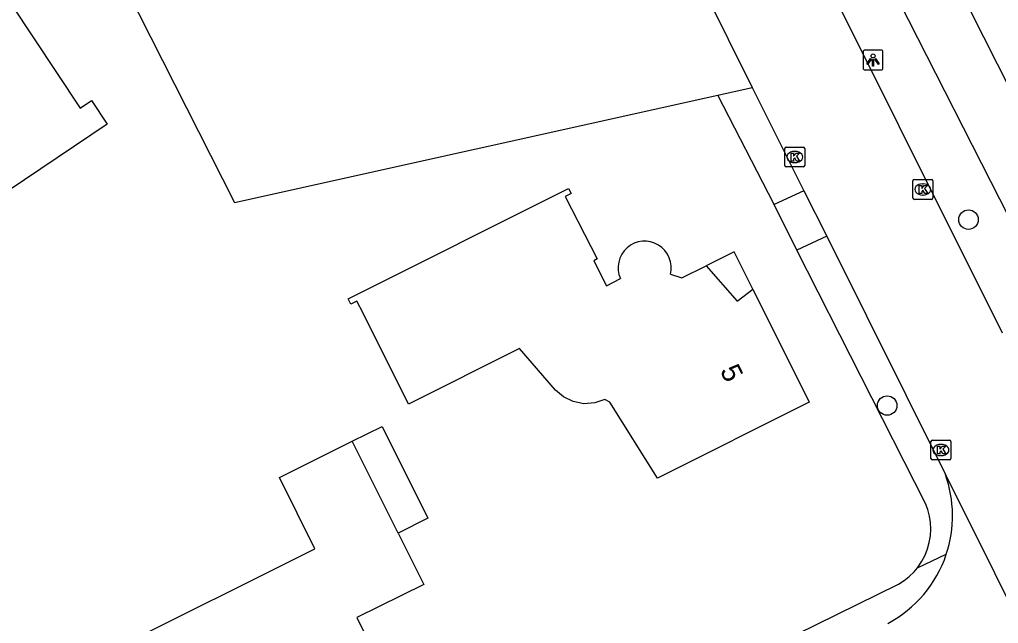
# Model space of a CAD drawing. Extents: x 157321 to 158827, y 386650 to 388532.
# Drawn here: x 158190.6 to 158239.72, y 387151.98 to 387182.26 of the extents above; entities that cross this region are included whole.
import ezdxf

# ---------------------------------------------------------------- set-up
doc = ezdxf.new("R2010")
doc.units = 0
for name, color, linetype in [('IMGEO_Berm_groen', 7, 'Continuous'), ('IMGEO_Boom', 7, 'Continuous'), ('IMGEO_Groenvoorziening', 7, 'Continuous'), ('IMGEO_Kolk', 7, 'Continuous'), ('IMGEO_Lichtpunt', 7, 'Continuous'), ('IMGEO_Pand', 7, 'Continuous'), ('IMGEO_Pand_nummerreeks', 7, 'Continuous'), ('IMGEO_Pand_overbouw', 7, 'Continuous'), ('IMGEO_Parkeervlak_open', 7, 'Continuous'), ('IMGEO_Rijbaan_lokaal_gesloten', 7, 'Continuous'), ('IMGEO_Voetpad_open', 7, 'Continuous')]:
    doc.layers.add(name, color=color, linetype=linetype)

msp = doc.modelspace()

# ---------------------------------------------------------------- linework, layer by layer
at = {"layer": 'IMGEO_Berm_groen'}
msp.add_lwpolyline([(158232.002, 387188.552), (158242.522, 387167.891)], dxfattribs=at)
at = {"layer": 'IMGEO_Boom'}
for centre in [(158238.22, 387172.232), (158234.139, 387162.905)]:
    msp.add_circle(centre, 0.489, dxfattribs=at)
at = {"layer": 'IMGEO_Groenvoorziening'}
for points in [[(158228.461, 387172.993), (158225.64, 387178.479)], [(158235.655, 387154.773), (158235.883, 387155.106), (158236.038, 387155.403), (158236.16, 387155.714), (158236.249, 387156.036), (158236.304, 387156.365), (158236.324, 387156.699), (158236.31, 387157.033), (158236.26, 387157.364), (158236.176, 387157.687), (158236.059, 387158), (158229.598, 387170.706)], [(158235.655, 387154.773), (158237.106, 387155.45)], [(158215.288, 387144.405), (158234.705, 387153.947), (158234.987, 387154.127), (158235.248, 387154.335), (158235.487, 387154.569), (158235.655, 387154.773)]]:
    msp.add_lwpolyline(points, dxfattribs=at)
at = {"layer": 'IMGEO_Kolk'}
for p, q in [((158228.998, 387174.945), (158228.998, 387175.797)), ((158229.073, 387175.871), (158229.925, 387175.871)), ((158229.486, 387175.651), (158229.511, 387175.651)), ((158229.999, 387175.797), (158229.999, 387174.945)), ((158229.925, 387174.871), (158229.073, 387174.871)), ((158229.509, 387175.091), (158229.484, 387175.091)), ((158235.427, 387173.318), (158235.427, 387174.17)), ((158235.502, 387174.244), (158236.354, 387174.244)), ((158236.428, 387174.17), (158236.428, 387173.318)), ((158235.915, 387174.024), (158235.94, 387174.024)), ((158236.354, 387173.244), (158235.502, 387173.244)), ((158235.938, 387173.464), (158235.913, 387173.464)), ((158236.335, 387160.25), (158236.335, 387161.102)), ((158236.41, 387161.176), (158237.262, 387161.176)), ((158236.823, 387160.956), (158236.848, 387160.956)), ((158237.336, 387161.102), (158237.336, 387160.25)), ((158237.262, 387160.176), (158236.41, 387160.176)), ((158236.846, 387160.396), (158236.821, 387160.396))]:
    msp.add_line(p, q, dxfattribs=at)
for points in [[(158228.998, 387174.945), (158228.998, 387175.797)], [(158229.073, 387175.871), (158229.925, 387175.871)], [(158229.999, 387175.797), (158229.999, 387174.945)], [(158229.319, 387175.571), (158229.442, 387175.571), (158229.442, 387175.42), (158229.572, 387175.571), (158229.736, 387175.571), (158229.59, 387175.42), (158229.743, 387175.171), (158229.591, 387175.171), (158229.506, 387175.335), (158229.442, 387175.268), (158229.442, 387175.171), (158229.319, 387175.171), (158229.319, 387175.571)], [(158229.925, 387174.871), (158229.073, 387174.871)], [(158235.427, 387173.318), (158235.427, 387174.17)], [(158235.502, 387174.244), (158236.354, 387174.244)], [(158236.428, 387174.17), (158236.428, 387173.318)], [(158235.748, 387173.944), (158235.871, 387173.944), (158235.871, 387173.793), (158236.001, 387173.944), (158236.165, 387173.944), (158236.019, 387173.793), (158236.172, 387173.544), (158236.02, 387173.544), (158235.935, 387173.708), (158235.871, 387173.641), (158235.871, 387173.544), (158235.748, 387173.544), (158235.748, 387173.944)], [(158236.354, 387173.244), (158235.502, 387173.244)], [(158236.335, 387160.25), (158236.335, 387161.102)], [(158236.41, 387161.176), (158237.262, 387161.176)], [(158237.336, 387161.102), (158237.336, 387160.25)], [(158236.656, 387160.876), (158236.779, 387160.876), (158236.779, 387160.725), (158236.909, 387160.876), (158237.073, 387160.876), (158236.927, 387160.725), (158237.08, 387160.476), (158236.928, 387160.476), (158236.843, 387160.64), (158236.779, 387160.573), (158236.779, 387160.476), (158236.656, 387160.476), (158236.656, 387160.876)], [(158237.262, 387160.176), (158236.41, 387160.176)]]:
    msp.add_lwpolyline(points, dxfattribs=at)
for centre, start, end in [((158229.075, 387175.795), 91.552, 178.448), ((158229.075, 387175.795), 91.552, 178.448), ((158229.923, 387175.795), 1.552, 88.448), ((158229.923, 387175.795), 1.552, 88.448), ((158229.075, 387174.947), 181.552, 268.448), ((158229.075, 387174.947), 181.552, 268.448), ((158229.923, 387174.947), 271.552, 358.448), ((158229.923, 387174.947), 271.552, 358.448), ((158235.504, 387174.168), 91.552, 178.448), ((158235.504, 387174.168), 91.552, 178.448), ((158236.352, 387174.168), 1.552, 88.448), ((158236.352, 387174.168), 1.552, 88.448), ((158235.504, 387173.32), 181.552, 268.448), ((158235.504, 387173.32), 181.552, 268.448), ((158236.352, 387173.32), 271.552, 358.448), ((158236.352, 387173.32), 271.552, 358.448), ((158236.412, 387161.1), 91.552, 178.448), ((158236.412, 387161.1), 91.552, 178.448), ((158237.26, 387161.1), 1.552, 88.448), ((158237.26, 387161.1), 1.552, 88.448), ((158236.412, 387160.252), 181.552, 268.448), ((158236.412, 387160.252), 181.552, 268.448), ((158237.26, 387160.252), 271.552, 358.448), ((158237.26, 387160.252), 271.552, 358.448)]:
    msp.add_arc(centre, 0.0765, start, end, dxfattribs=at)
for centre, major_axis, ratio, start_param, end_param in [((158229.485, 387175.371), (-0.387, 0.002), 0.722429, 4.712389, 7.853982), ((158229.51, 387175.371), (-0.39, 0.002), 0.717154, 1.570796, 4.712389), ((158235.914, 387173.744), (-0.387, 0.002), 0.722429, 4.712389, 7.853982), ((158235.939, 387173.744), (-0.39, 0.002), 0.717154, 1.570796, 4.712389), ((158236.822, 387160.676), (-0.387, 0.002), 0.722429, 4.712389, 7.853982), ((158236.847, 387160.676), (-0.39, 0.002), 0.717154, 1.570796, 4.712389)]:
    msp.add_ellipse(centre, major_axis=major_axis, ratio=ratio, start_param=start_param, end_param=end_param, dxfattribs=at)
at = {"layer": 'IMGEO_Lichtpunt'}
for p, q in [((158232.931, 387180.641), (158232.931, 387179.834)), ((158232.931, 387180.641), (158232.931, 387179.834)), ((158233.833, 387180.736), (158233.025, 387180.736)), ((158233.833, 387180.736), (158233.025, 387180.736)), ((158233.927, 387179.834), (158233.927, 387180.641)), ((158233.927, 387179.834), (158233.927, 387180.641)), ((158233.025, 387179.74), (158233.833, 387179.74)), ((158233.025, 387179.74), (158233.833, 387179.74))]:
    msp.add_line(p, q, dxfattribs=at)
for points in [[(158233.305, 387180.305), (158233.344, 387180.277), (158233.156, 387180.015), (158233.118, 387180.042), (158233.305, 387180.305)], [(158233.407, 387180.257), (158233.454, 387180.257), (158233.454, 387179.935), (158233.407, 387179.935), (158233.407, 387180.257)], [(158233.517, 387180.277), (158233.555, 387180.304), (158233.742, 387180.042), (158233.703, 387180.014), (158233.517, 387180.277)]]:
    msp.add_lwpolyline(points, dxfattribs=at)
msp.add_circle((158233.43, 387180.439), 0.0994, dxfattribs=at)
for centre, start, end in [((158233.025, 387180.641), 90, 180), ((158233.025, 387180.641), 90, 180), ((158233.833, 387180.641), 0, 90), ((158233.833, 387180.641), 0, 90), ((158233.025, 387179.834), 180, 270), ((158233.025, 387179.834), 180, 270), ((158233.833, 387179.834), 270, 0), ((158233.833, 387179.834), 270, 360)]:
    msp.add_arc(centre, 0.0946, start, end, dxfattribs=at)
at = {"layer": 'IMGEO_Pand'}
for points in [[(158251.152, 387195.446), (158248.734, 387194.228), (158243.529, 387191.607), (158247.974, 387182.784), (158253.142, 387185.384), (158255.644, 387180.411), (158248.283, 387176.708), (158243.816, 387174.461), (158241.391, 387179.203), (158240.357, 387178.677), (158236.258, 387186.782), (158237.319, 387187.324), (158238.237, 387187.793), (158237.424, 387189.402), (158236.508, 387188.936), (158235.792, 387190.374), (158237.759, 387191.367), (158235.863, 387195.124), (158245.553, 387200.004), (158245.769, 387200.113), (158248.099, 387201.286), (158249.098, 387199.374)], [(158178.524, 387186.149), (158176.322, 387190.638), (158179.847, 387192.398), (158179.547, 387192.866), (158183.49, 387195.479), (158184.978, 387193.274), (158187.23, 387194.407), (158191.447, 387186.111), (158189.583, 387185.163), (158188.965, 387184.849), (158193.64, 387177.822), (158194.214, 387178.203), (158195, 387177.021), (158190.851, 387174.232), (158188.72, 387172.8), (158181.916, 387182.662), (158180.559, 387181.999), (158178.524, 387186.149)], [(158223.256, 387169.49), (158223.831, 387169.306), (158225.06, 387169.919), (158226.609, 387168.146), (158227.398, 387168.743), (158230.223, 387163.077), (158222.613, 387159.264), (158220.226, 387163.082), (158219.975, 387163.212), (158219.463, 387163.037), (158218.911, 387162.987), (158218.376, 387163.107), (158217.894, 387163.345), (158217.497, 387163.682), (158215.687, 387165.76), (158210.123, 387162.978), (158207.833, 387167.531), (158207.523, 387168.147), (158207.22, 387167.996), (158207.086, 387168.264), (158218.142, 387173.797)], [(158218.142, 387173.797), (158218.272, 387173.54), (158217.983, 387173.394), (158219.58, 387170.262), (158219.41, 387170.158), (158220.045, 387168.915), (158220.748, 387169.275)], [(158207.296, 387161.111), (158208.786, 387161.852), (158211.081, 387157.26), (158209.598, 387156.506)], [(158209.598, 387156.506), (158210.886, 387153.93), (158207.518, 387152.267), (158208.863, 387149.543), (158209.551, 387148.149), (158199.073, 387142.942), (158196.835, 387147.413), (158195.221, 387150.638), (158205.418, 387155.712), (158203.638, 387159.29), (158207.296, 387161.111)], [(158209.598, 387156.506), (158207.296, 387161.111)]]:
    msp.add_lwpolyline(points, dxfattribs=at)
msp.add_arc((158221.965, 387169.818), 1.332, 345.7324, 204.0671, dxfattribs=at)
at = {"layer": 'IMGEO_Pand_overbouw'}
msp.add_lwpolyline([(158226.463, 387170.619), (158225.06, 387169.919), (158226.609, 387168.146), (158227.398, 387168.743)], close=True, dxfattribs=at)
at = {"layer": 'IMGEO_Parkeervlak_open'}
for points in [[(158180.674, 387214.601), (158180.644, 387214.276), (158193.399, 387188.847), (158194.761, 387186.161), (158201.391, 387173.082), (158225.64, 387178.479)], [(158225.64, 387178.479), (158227.354, 387178.86)]]:
    msp.add_lwpolyline(points, dxfattribs=at)
at = {"layer": 'IMGEO_Rijbaan_lokaal_gesloten'}
for points in [[(158222.532, 387188.602), (158227.354, 387178.86)], [(158239.92, 387166.54), (158229.541, 387187.344)], [(158227.354, 387178.86), (158229.963, 387173.679)], [(158229.963, 387173.679), (158231.104, 387171.408)], [(158231.104, 387171.408), (158237.057, 387159.45)], [(158237.057, 387159.45), (158244.461, 387144.615)]]:
    msp.add_lwpolyline(points, dxfattribs=at)
for centre, radius, start, end in [((158231.306, 387157.379), 6.112, 341.6008, 19.8029), ((158231.303, 387157.381), 6.116, 297.9326, 341.5917)]:
    msp.add_arc(centre, radius, start, end, dxfattribs=at)
at = {"layer": 'IMGEO_Voetpad_open'}
for points in [[(158229.963, 387173.679), (158228.461, 387172.993)], [(158229.598, 387170.706), (158228.461, 387172.993)], [(158231.104, 387171.408), (158229.598, 387170.706)]]:
    msp.add_lwpolyline(points, dxfattribs=at)

# ---------------------------------------------------------------- texts
at = {"layer": 'IMGEO_Pand_nummerreeks'}
msp.add_text('5', height=1, rotation=295.9189, dxfattribs=at).set_placement((158225.733, 387164.662))

doc.saveas('drawing.dxf')
